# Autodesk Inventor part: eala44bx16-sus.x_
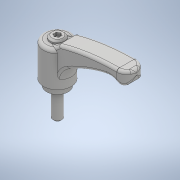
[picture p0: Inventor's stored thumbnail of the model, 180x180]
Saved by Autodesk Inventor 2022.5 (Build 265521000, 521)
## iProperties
Created: 2018-05
Part Number: eala44bx16-sus.x_
Material: 一般
Document SubType Name: Modeling
Designer: imaocorp
Density: 1 g/cm^3
Appearance: 既定
Sending System: SOLIDWORKS 2016-2016286
MC: AMD64
MC_MODEL: AMD64 Family 21 Model 2 Stepping 0, AuthenticAMD
OS: Windows_NT
FRU: Parasolid Version 28.0, build 224,  7-29-2016
FORMAT: text
GUISE: transmit
KEY: eala44bx16-sus
FILE: eala44bx16-sus.x_t
DATE: Fri May 18 11:28:09 2018
Author: imaocorp
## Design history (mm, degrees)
feature "Base1"
node "ソリッド1"
